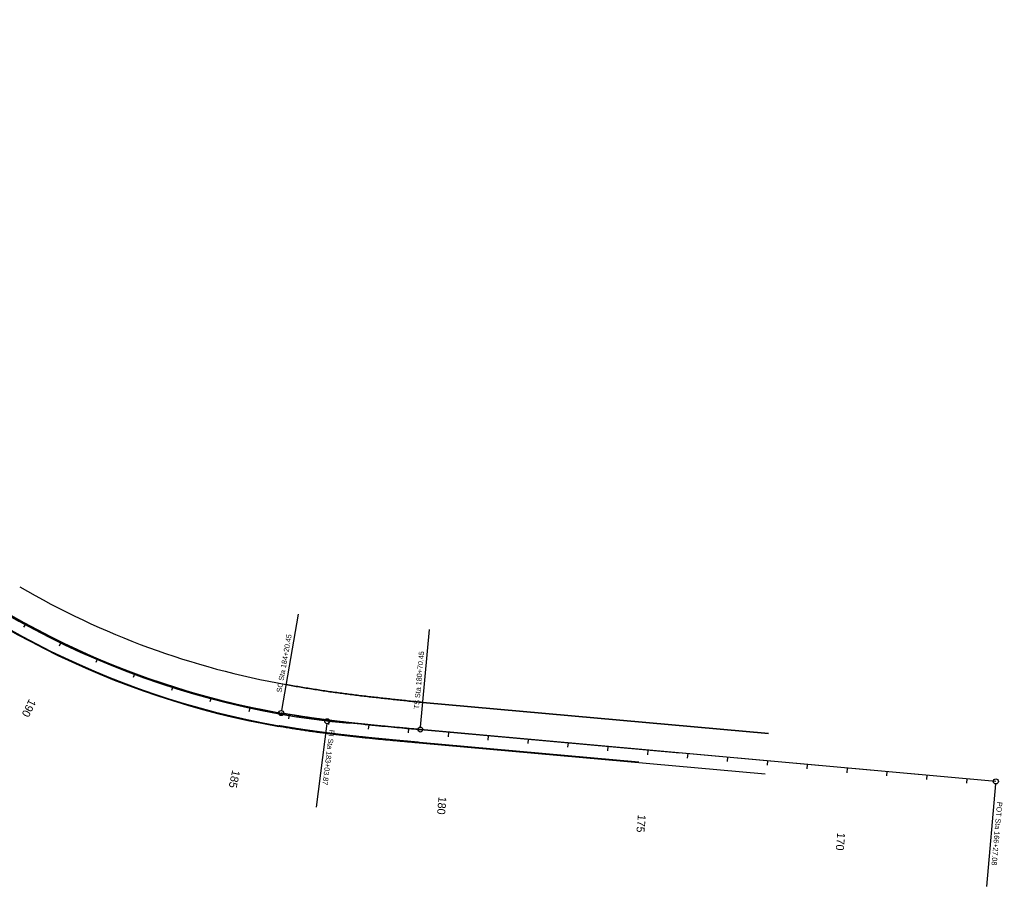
# Model space of a CAD drawing. Extents: x 5180909 to 5237144, y 3695282 to 3720102.
# Drawn here: x 5198956 to 5201411, y 3702372 to 3704537 of the extents above; entities that cross this region are included whole.
import ezdxf

# ---------------------------------------------------------------- set-up
doc = ezdxf.new("R2010")
doc.units = 0
for name, color, linetype in [('Alignment', 7, 'Continuous'), ('brgPreStructureNew', 7, 'Continuous'), ('Default', 7, 'Continuous'), ('DisFieldPoint', 7, 'Continuous'), ('dsnEntrancePaved', 7, 'Continuous'), ('dsnShadingGranular', 7, 'Continuous'), ('dsnSidewalkShadingRamp', 7, 'Continuous'), ('dsnStgShadingPropGrdLim', 7, 'Continuous')]:
    doc.layers.add(name, color=color, linetype=linetype)

msp = doc.modelspace()

# ---------------------------------------------------------------- linework, layer by layer
at = {"layer": 'Alignment'}
msp.add_line((5201394.7, 3702633.9), (5199957.1, 3702763.5), dxfattribs=at)
msp.add_arc((5199969.8, 3704853.2), 2080, 193.5037, 260.0302, dxfattribs=at)
msp.add_open_spline([(5199957.1, 3702763.5), (5199947.4, 3702764.4), (5199928.1, 3702766.1), (5199889.3, 3702769.6), (5199840.9, 3702774.2), (5199782.9, 3702780.3), (5199725, 3702787.1), (5199676.8, 3702793.8), (5199638.4, 3702799.7), (5199619.2, 3702803), (5199609.7, 3702804.7)], degree=3, dxfattribs=at)
at = {"layer": 'brgPreStructureNew'}
msp.add_open_spline([(5199957.5, 3702763.2), (5199956, 3702763.4), (5199954.4, 3702763.5), (5199952.8, 3702763.7), (5199951.3, 3702763.8), (5199949.7, 3702763.9), (5199948.1, 3702764.1), (5199946.5, 3702764.2), (5199945, 3702764.4), (5199943.4, 3702764.5), (5199941.8, 3702764.6), (5199940.3, 3702764.8), (5199938.7, 3702764.9), (5199937.1, 3702765.1), (5199935.6, 3702765.2), (5199934, 3702765.4), (5199932.4, 3702765.5), (5199930.8, 3702765.6), (5199929.3, 3702765.8), (5199927.7, 3702765.9), (5199926.1, 3702766.1), (5199924.6, 3702766.2), (5199923, 3702766.4), (5199921.4, 3702766.5), (5199919.9, 3702766.6), (5199918.3, 3702766.8), (5199916.7, 3702766.9), (5199915.1, 3702767.1), (5199913.6, 3702767.2), (5199912, 3702767.4), (5199910.4, 3702767.5), (5199908.9, 3702767.6), (5199907.3, 3702767.8), (5199905.7, 3702767.9), (5199904.2, 3702768.1), (5199902.6, 3702768.2), (5199901, 3702768.4), (5199899.4, 3702768.5), (5199897.9, 3702768.7), (5199896.3, 3702768.8), (5199894.7, 3702768.9), (5199893.2, 3702769.1), (5199891.6, 3702769.2), (5199890, 3702769.4), (5199888.5, 3702769.5), (5199886.9, 3702769.7), (5199885.3, 3702769.8), (5199883.7, 3702770), (5199882.2, 3702770.1), (5199880.6, 3702770.3), (5199879, 3702770.4), (5199877.5, 3702770.6), (5199875.9, 3702770.7), (5199874.3, 3702770.9), (5199872.8, 3702771), (5199871.2, 3702771.2), (5199869.6, 3702771.3), (5199868, 3702771.5), (5199866.5, 3702771.6), (5199864.9, 3702771.8), (5199863.3, 3702771.9), (5199861.8, 3702772.1), (5199860.2, 3702772.2), (5199858.6, 3702772.4), (5199857.1, 3702772.5), (5199855.5, 3702772.7), (5199853.9, 3702772.8), (5199852.4, 3702773), (5199850.8, 3702773.1), (5199849.2, 3702773.3), (5199847.6, 3702773.4), (5199846.1, 3702773.6), (5199844.5, 3702773.8), (5199842.9, 3702773.9), (5199841.4, 3702774.1), (5199839.8, 3702774.2), (5199838.2, 3702774.4), (5199836.7, 3702774.5), (5199835.1, 3702774.7), (5199833.5, 3702774.9), (5199832, 3702775), (5199830.4, 3702775.2), (5199828.8, 3702775.3), (5199827.3, 3702775.5), (5199825.7, 3702775.7), (5199824.1, 3702775.8), (5199822.5, 3702776), (5199821, 3702776.1), (5199819.4, 3702776.3), (5199817.8, 3702776.5), (5199816.3, 3702776.6), (5199814.7, 3702776.8), (5199813.1, 3702776.9), (5199811.6, 3702777.1), (5199810, 3702777.3), (5199808.4, 3702777.4), (5199806.9, 3702777.6), (5199805.3, 3702777.8), (5199803.7, 3702777.9), (5199802.2, 3702778.1), (5199800.6, 3702778.3), (5199799, 3702778.4), (5199797.5, 3702778.6), (5199795.9, 3702778.8), (5199794.3, 3702779), (5199792.8, 3702779.1), (5199791.2, 3702779.3), (5199789.6, 3702779.5), (5199788.1, 3702779.6), (5199786.5, 3702779.8), (5199784.9, 3702780), (5199783.4, 3702780.2), (5199781.8, 3702780.3), (5199780.2, 3702780.5), (5199778.7, 3702780.7), (5199777.1, 3702780.9), (5199775.5, 3702781), (5199774, 3702781.2), (5199772.4, 3702781.4), (5199770.8, 3702781.6), (5199769.3, 3702781.8), (5199767.7, 3702781.9), (5199766.1, 3702782.1), (5199764.6, 3702782.3), (5199763, 3702782.5), (5199761.4, 3702782.7), (5199759.9, 3702782.9), (5199758.3, 3702783), (5199756.7, 3702783.2), (5199755.2, 3702783.4), (5199753.6, 3702783.6), (5199752, 3702783.8), (5199750.5, 3702784), (5199748.9, 3702784.2), (5199747.3, 3702784.3), (5199745.8, 3702784.5), (5199744.2, 3702784.7), (5199742.6, 3702784.9), (5199741.1, 3702785.1), (5199739.5, 3702785.3), (5199738, 3702785.5), (5199736.4, 3702785.7), (5199734.8, 3702785.9), (5199733.3, 3702786.1), (5199731.7, 3702786.3), (5199730.1, 3702786.5), (5199728.6, 3702786.7), (5199727, 3702786.9), (5199725.4, 3702787.1), (5199723.9, 3702787.3), (5199722.3, 3702787.5), (5199720.7, 3702787.7), (5199719.2, 3702787.9), (5199717.6, 3702788.1), (5199716.1, 3702788.3), (5199714.5, 3702788.5), (5199712.9, 3702788.7), (5199711.4, 3702788.9), (5199709.8, 3702789.1), (5199708.2, 3702789.3), (5199706.7, 3702789.5), (5199705.1, 3702789.7), (5199703.6, 3702790), (5199702, 3702790.2), (5199700.4, 3702790.4), (5199698.9, 3702790.6), (5199697.3, 3702790.8), (5199695.7, 3702791), (5199694.2, 3702791.2), (5199692.6, 3702791.5), (5199691.1, 3702791.7), (5199689.5, 3702791.9), (5199687.9, 3702792.1), (5199686.4, 3702792.3), (5199684.8, 3702792.6), (5199683.3, 3702792.8), (5199681.7, 3702793), (5199680.1, 3702793.2), (5199678.6, 3702793.5), (5199677, 3702793.7), (5199675.5, 3702793.9), (5199673.9, 3702794.1), (5199672.3, 3702794.4), (5199670.8, 3702794.6), (5199669.2, 3702794.8), (5199667.7, 3702795.1), (5199666.1, 3702795.3), (5199664.5, 3702795.5), (5199663, 3702795.8), (5199661.4, 3702796), (5199659.9, 3702796.2), (5199658.3, 3702796.5), (5199656.7, 3702796.7), (5199655.2, 3702797), (5199653.6, 3702797.2), (5199652.1, 3702797.4), (5199650.5, 3702797.7), (5199649, 3702797.9), (5199647.4, 3702798.2), (5199645.8, 3702798.4), (5199644.3, 3702798.7), (5199642.7, 3702798.9), (5199641.2, 3702799.2), (5199639.6, 3702799.4), (5199638.1, 3702799.7), (5199636.5, 3702799.9), (5199634.9, 3702800.2), (5199633.4, 3702800.4), (5199631.8, 3702800.7), (5199630.3, 3702800.9), (5199628.7, 3702801.2), (5199627.2, 3702801.5), (5199625.6, 3702801.7), (5199624.1, 3702802), (5199622.5, 3702802.3), (5199620.9, 3702802.5), (5199619.4, 3702802.8), (5199617.8, 3702803), (5199616.3, 3702803.3), (5199614.7, 3702803.6), (5199613.2, 3702803.9), (5199611.6, 3702804.1), (5199610.1, 3702804.4)], degree=3, dxfattribs=at)
msp.add_open_spline([(5199957.5, 3702763.2), (5199956, 3702763.4), (5199954.4, 3702763.5), (5199952.8, 3702763.7), (5199951.3, 3702763.8), (5199949.7, 3702763.9), (5199948.1, 3702764.1), (5199946.5, 3702764.2), (5199945, 3702764.4), (5199943.4, 3702764.5), (5199941.8, 3702764.6), (5199940.3, 3702764.8), (5199938.7, 3702764.9), (5199937.1, 3702765.1), (5199935.6, 3702765.2), (5199934, 3702765.4), (5199932.4, 3702765.5), (5199930.8, 3702765.6), (5199929.3, 3702765.8), (5199927.7, 3702765.9), (5199926.1, 3702766.1), (5199924.6, 3702766.2), (5199923, 3702766.4), (5199921.4, 3702766.5), (5199919.9, 3702766.6), (5199918.3, 3702766.8), (5199916.7, 3702766.9), (5199915.1, 3702767.1), (5199913.6, 3702767.2), (5199912, 3702767.4), (5199910.4, 3702767.5), (5199908.9, 3702767.6), (5199907.3, 3702767.8), (5199905.7, 3702767.9), (5199904.2, 3702768.1), (5199902.6, 3702768.2), (5199901, 3702768.4), (5199899.4, 3702768.5), (5199897.9, 3702768.7), (5199896.3, 3702768.8), (5199894.7, 3702768.9), (5199893.2, 3702769.1), (5199891.6, 3702769.2), (5199890, 3702769.4), (5199888.5, 3702769.5), (5199886.9, 3702769.7), (5199885.3, 3702769.8), (5199883.7, 3702770), (5199882.2, 3702770.1), (5199880.6, 3702770.3), (5199879, 3702770.4), (5199877.5, 3702770.6), (5199875.9, 3702770.7), (5199874.3, 3702770.9), (5199872.8, 3702771), (5199871.2, 3702771.2), (5199869.6, 3702771.3), (5199868, 3702771.5), (5199866.5, 3702771.6), (5199864.9, 3702771.8), (5199863.3, 3702771.9), (5199861.8, 3702772.1), (5199860.2, 3702772.2), (5199858.6, 3702772.4), (5199857.1, 3702772.5), (5199855.5, 3702772.7), (5199853.9, 3702772.8), (5199852.4, 3702773), (5199850.8, 3702773.1), (5199849.2, 3702773.3), (5199847.6, 3702773.4), (5199846.1, 3702773.6), (5199844.5, 3702773.8), (5199842.9, 3702773.9), (5199841.4, 3702774.1), (5199839.8, 3702774.2), (5199838.2, 3702774.4), (5199836.7, 3702774.5), (5199835.1, 3702774.7), (5199833.5, 3702774.9), (5199832, 3702775), (5199830.4, 3702775.2), (5199828.8, 3702775.3), (5199827.3, 3702775.5), (5199825.7, 3702775.7), (5199824.1, 3702775.8), (5199822.5, 3702776), (5199821, 3702776.1), (5199819.4, 3702776.3), (5199817.8, 3702776.5), (5199816.3, 3702776.6), (5199814.7, 3702776.8), (5199813.1, 3702776.9), (5199811.6, 3702777.1), (5199810, 3702777.3), (5199808.4, 3702777.4), (5199806.9, 3702777.6), (5199805.3, 3702777.8), (5199803.7, 3702777.9), (5199802.2, 3702778.1), (5199800.6, 3702778.3), (5199799, 3702778.4), (5199797.5, 3702778.6), (5199795.9, 3702778.8), (5199794.3, 3702779), (5199792.8, 3702779.1), (5199791.2, 3702779.3), (5199789.6, 3702779.5), (5199788.1, 3702779.6), (5199786.5, 3702779.8), (5199784.9, 3702780), (5199783.4, 3702780.2), (5199781.8, 3702780.3), (5199780.2, 3702780.5), (5199778.7, 3702780.7), (5199777.1, 3702780.9), (5199775.5, 3702781), (5199774, 3702781.2), (5199772.4, 3702781.4), (5199770.8, 3702781.6), (5199769.3, 3702781.8), (5199767.7, 3702781.9), (5199766.1, 3702782.1), (5199764.6, 3702782.3), (5199763, 3702782.5), (5199761.4, 3702782.7), (5199759.9, 3702782.9), (5199758.3, 3702783), (5199756.7, 3702783.2), (5199755.2, 3702783.4), (5199753.6, 3702783.6), (5199752, 3702783.8), (5199750.5, 3702784), (5199748.9, 3702784.2), (5199747.3, 3702784.3), (5199745.8, 3702784.5), (5199744.2, 3702784.7), (5199742.6, 3702784.9), (5199741.1, 3702785.1), (5199739.5, 3702785.3), (5199738, 3702785.5), (5199736.4, 3702785.7), (5199734.8, 3702785.9), (5199733.3, 3702786.1), (5199731.7, 3702786.3), (5199730.1, 3702786.5), (5199728.6, 3702786.7), (5199727, 3702786.9), (5199725.4, 3702787.1), (5199723.9, 3702787.3), (5199722.3, 3702787.5), (5199720.7, 3702787.7), (5199719.2, 3702787.9), (5199717.6, 3702788.1), (5199716.1, 3702788.3), (5199714.5, 3702788.5), (5199712.9, 3702788.7), (5199711.4, 3702788.9), (5199709.8, 3702789.1), (5199708.2, 3702789.3), (5199706.7, 3702789.5), (5199705.1, 3702789.7), (5199703.6, 3702790), (5199702, 3702790.2), (5199700.4, 3702790.4), (5199698.9, 3702790.6), (5199697.3, 3702790.8), (5199695.7, 3702791), (5199694.2, 3702791.2), (5199692.6, 3702791.5), (5199691.1, 3702791.7), (5199689.5, 3702791.9), (5199687.9, 3702792.1), (5199686.4, 3702792.3), (5199684.8, 3702792.6), (5199683.3, 3702792.8), (5199681.7, 3702793), (5199680.1, 3702793.2), (5199678.6, 3702793.5), (5199677, 3702793.7), (5199675.5, 3702793.9), (5199673.9, 3702794.1), (5199672.3, 3702794.4), (5199670.8, 3702794.6), (5199669.2, 3702794.8), (5199667.7, 3702795.1), (5199666.1, 3702795.3), (5199664.5, 3702795.5), (5199663, 3702795.8), (5199661.4, 3702796), (5199659.9, 3702796.2), (5199658.3, 3702796.5), (5199656.7, 3702796.7), (5199655.2, 3702797), (5199653.6, 3702797.2), (5199652.1, 3702797.4), (5199650.5, 3702797.7), (5199649, 3702797.9), (5199647.4, 3702798.2), (5199645.8, 3702798.4), (5199644.3, 3702798.7), (5199642.7, 3702798.9), (5199641.2, 3702799.2), (5199639.6, 3702799.4), (5199638.1, 3702799.7), (5199636.5, 3702799.9), (5199634.9, 3702800.2), (5199633.4, 3702800.4), (5199631.8, 3702800.7), (5199630.3, 3702800.9), (5199628.7, 3702801.2), (5199627.2, 3702801.5), (5199625.6, 3702801.7), (5199624.1, 3702802), (5199622.5, 3702802.3), (5199620.9, 3702802.5), (5199619.4, 3702802.8), (5199617.8, 3702803), (5199616.3, 3702803.3), (5199614.7, 3702803.6), (5199613.2, 3702803.9), (5199611.6, 3702804.1), (5199610.1, 3702804.4)], degree=3, dxfattribs=at)
at = {"layer": 'Default'}
msp.add_arc((5199969.8, 3704853.2), 2080, 193.5037, 260.0302, dxfattribs=at)
at = {"layer": 'DisFieldPoint'}
for p, q in [((5199604.6, 3702772.9), (5199604.5, 3702772.9)), ((5199604.6, 3702772.9), (5199604.6, 3702772.9)), ((5200605, 3702704.8), (5199957.5, 3702763.2)), ((5200502.5, 3702681.9), (5199954.7, 3702731.4))]:
    msp.add_line(p, q, dxfattribs=at)
for radius in [2083.5, 2115.5]:
    msp.add_arc((5199970.6, 3704856.4), radius, 191.1921, 260.0343, dxfattribs=at)
msp.add_open_spline([(5199954.7, 3702731.4), (5199953.1, 3702731.5), (5199951.5, 3702731.6), (5199949.9, 3702731.8), (5199948.4, 3702731.9), (5199946.8, 3702732.1), (5199945.2, 3702732.2), (5199943.7, 3702732.3), (5199942.1, 3702732.5), (5199940.5, 3702732.6), (5199939, 3702732.8), (5199937.4, 3702732.9), (5199935.8, 3702733.1), (5199934.2, 3702733.2), (5199932.7, 3702733.3), (5199931.1, 3702733.5), (5199929.5, 3702733.6), (5199928, 3702733.8), (5199926.4, 3702733.9), (5199924.8, 3702734.1), (5199923.2, 3702734.2), (5199921.7, 3702734.3), (5199920.1, 3702734.5), (5199918.5, 3702734.6), (5199916.9, 3702734.8), (5199915.4, 3702734.9), (5199913.8, 3702735.1), (5199912.2, 3702735.2), (5199910.7, 3702735.3), (5199909.1, 3702735.5), (5199907.5, 3702735.6), (5199905.9, 3702735.8), (5199904.4, 3702735.9), (5199902.8, 3702736.1), (5199901.2, 3702736.2), (5199899.6, 3702736.4), (5199898.1, 3702736.5), (5199896.5, 3702736.6), (5199894.9, 3702736.8), (5199893.3, 3702736.9), (5199891.8, 3702737.1), (5199890.2, 3702737.2), (5199888.6, 3702737.4), (5199887, 3702737.5), (5199885.5, 3702737.7), (5199883.9, 3702737.8), (5199882.3, 3702738), (5199880.7, 3702738.1), (5199879.2, 3702738.3), (5199877.6, 3702738.4), (5199876, 3702738.6), (5199874.4, 3702738.7), (5199872.9, 3702738.9), (5199871.3, 3702739), (5199869.7, 3702739.2), (5199868.1, 3702739.3), (5199866.6, 3702739.5), (5199865, 3702739.6), (5199863.4, 3702739.8), (5199861.8, 3702739.9), (5199860.3, 3702740.1), (5199858.7, 3702740.2), (5199857.1, 3702740.4), (5199855.5, 3702740.5), (5199854, 3702740.7), (5199852.4, 3702740.8), (5199850.8, 3702741), (5199849.2, 3702741.1), (5199847.7, 3702741.3), (5199846.1, 3702741.4), (5199844.5, 3702741.6), (5199842.9, 3702741.8), (5199841.4, 3702741.9), (5199839.8, 3702742.1), (5199838.2, 3702742.2), (5199836.6, 3702742.4), (5199835, 3702742.5), (5199833.5, 3702742.7), (5199831.9, 3702742.9), (5199830.3, 3702743), (5199828.7, 3702743.2), (5199827.2, 3702743.3), (5199825.6, 3702743.5), (5199824, 3702743.7), (5199822.4, 3702743.8), (5199820.9, 3702744), (5199819.3, 3702744.1), (5199817.7, 3702744.3), (5199816.1, 3702744.5), (5199814.5, 3702744.6), (5199813, 3702744.8), (5199811.4, 3702745), (5199809.8, 3702745.1), (5199808.2, 3702745.3), (5199806.7, 3702745.5), (5199805.1, 3702745.6), (5199803.5, 3702745.8), (5199801.9, 3702746), (5199800.3, 3702746.1), (5199798.8, 3702746.3), (5199797.2, 3702746.5), (5199795.6, 3702746.6), (5199794, 3702746.8), (5199792.4, 3702747), (5199790.9, 3702747.1), (5199789.3, 3702747.3), (5199787.7, 3702747.5), (5199786.1, 3702747.7), (5199784.6, 3702747.8), (5199783, 3702748), (5199781.4, 3702748.2), (5199779.8, 3702748.4), (5199778.2, 3702748.5), (5199776.7, 3702748.7), (5199775.1, 3702748.9), (5199773.5, 3702749.1), (5199771.9, 3702749.2), (5199770.3, 3702749.4), (5199768.8, 3702749.6), (5199767.2, 3702749.8), (5199765.6, 3702750), (5199764, 3702750.2), (5199762.4, 3702750.3), (5199760.9, 3702750.5), (5199759.3, 3702750.7), (5199757.7, 3702750.9), (5199756.1, 3702751.1), (5199754.5, 3702751.3), (5199753, 3702751.4), (5199751.4, 3702751.6), (5199749.8, 3702751.8), (5199748.2, 3702752), (5199746.7, 3702752.2), (5199745.1, 3702752.4), (5199743.5, 3702752.6), (5199741.9, 3702752.8), (5199740.3, 3702753), (5199738.8, 3702753.2), (5199737.2, 3702753.4), (5199735.6, 3702753.5), (5199734, 3702753.7), (5199732.4, 3702753.9), (5199730.9, 3702754.1), (5199729.3, 3702754.3), (5199727.7, 3702754.5), (5199726.1, 3702754.7), (5199724.5, 3702754.9), (5199723, 3702755.1), (5199721.4, 3702755.3), (5199719.8, 3702755.5), (5199718.2, 3702755.7), (5199716.6, 3702755.9), (5199715.1, 3702756.1), (5199713.5, 3702756.4), (5199711.9, 3702756.6), (5199710.3, 3702756.8), (5199708.7, 3702757), (5199707.2, 3702757.2), (5199705.6, 3702757.4), (5199704, 3702757.6), (5199702.4, 3702757.8), (5199700.8, 3702758), (5199699.3, 3702758.2), (5199697.7, 3702758.5), (5199696.1, 3702758.7), (5199694.5, 3702758.9), (5199692.9, 3702759.1), (5199691.4, 3702759.3), (5199689.8, 3702759.5), (5199688.2, 3702759.8), (5199686.6, 3702760), (5199685, 3702760.2), (5199683.5, 3702760.4), (5199681.9, 3702760.7), (5199680.3, 3702760.9), (5199678.7, 3702761.1), (5199677.1, 3702761.3), (5199675.6, 3702761.6), (5199674, 3702761.8), (5199672.4, 3702762), (5199670.8, 3702762.2), (5199669.2, 3702762.5), (5199667.7, 3702762.7), (5199666.1, 3702762.9), (5199664.5, 3702763.2), (5199662.9, 3702763.4), (5199661.3, 3702763.7), (5199659.8, 3702763.9), (5199658.2, 3702764.1), (5199656.6, 3702764.4), (5199655, 3702764.6), (5199653.5, 3702764.8), (5199651.9, 3702765.1), (5199650.3, 3702765.3), (5199648.7, 3702765.6), (5199647.1, 3702765.8), (5199645.6, 3702766.1), (5199644, 3702766.3), (5199642.4, 3702766.6), (5199640.8, 3702766.8), (5199639.2, 3702767.1), (5199637.7, 3702767.3), (5199636.1, 3702767.6), (5199634.5, 3702767.8), (5199632.9, 3702768.1), (5199631.4, 3702768.3), (5199629.8, 3702768.6), (5199628.2, 3702768.9), (5199626.6, 3702769.1), (5199625, 3702769.4), (5199623.5, 3702769.6), (5199621.9, 3702769.9), (5199620.3, 3702770.2), (5199618.7, 3702770.4), (5199617.2, 3702770.7), (5199615.6, 3702771), (5199614, 3702771.2), (5199612.4, 3702771.5), (5199610.9, 3702771.8), (5199609.2, 3702772.1), (5199607.7, 3702772.3), (5199606.1, 3702772.6), (5199604.6, 3702772.9)], degree=3, dxfattribs=at)
at = {"layer": 'dsnEntrancePaved'}
msp.add_arc((5199969.8, 3704853.2), 2080, 193.5037, 260.0302, dxfattribs=at)
msp.add_open_spline([(5199609.7, 3702804.7), (5199624, 3702802.1), (5199652.8, 3702797.4), (5199710.5, 3702788.9), (5199782.9, 3702780.1), (5199855.5, 3702772.8), (5199913.5, 3702767.4), (5199942.6, 3702764.8), (5199957.1, 3702763.5)], degree=3, dxfattribs=at)
at = {"layer": 'dsnShadingGranular'}
for p, q in [((5200826.4, 3702753.4), (5199963.2, 3702831.2)), ((5199963.2, 3702831.2), (5200826.4, 3702753.4)), ((5201394.7, 3702633.9), (5199780.9, 3702779.4)), ((5201394.7, 3702633.9), (5199957.1, 3702763.5)), ((5200818.3, 3702651.7), (5199954.1, 3702729.6))]:
    msp.add_line(p, q, dxfattribs=at)
for centre, radius, start, end in [((5199967.6, 3704851), 2080, 188.6831, 264.8508), ((5199969.8, 3704853.2), 2114, 193.5037, 260.0302), ((5199969.8, 3704853.2), 2007.5, 239.675, 260.0302), ((5199969.8, 3704853.2), 2007.5, 239.675, 260.0302)]:
    msp.add_arc(centre, radius, start, end, dxfattribs=at)
for points in [[(5199622.2, 3702876.1), (5199627.7, 3702875), (5199638.8, 3702872.9), (5199655.5, 3702870), (5199672.2, 3702867.2), (5199689, 3702864.5), (5199705.9, 3702861.9), (5199722.8, 3702859.3), (5199739.7, 3702856.9), (5199756.7, 3702854.6), (5199773.7, 3702852.4), (5199790.7, 3702850.2), (5199807.8, 3702848.1), (5199824.9, 3702846.1), (5199842.1, 3702844.1), (5199859.3, 3702842.2), (5199876.6, 3702840.3), (5199893.8, 3702838.4), (5199911.1, 3702836.6), (5199928.5, 3702834.8), (5199945.8, 3702833), (5199957.4, 3702831.8), (5199963.2, 3702831.2)], [(5199954.1, 3702729.6), (5199949.2, 3702730.1), (5199939.5, 3702730.9), (5199925, 3702732.3), (5199910.4, 3702733.6), (5199895.9, 3702734.9), (5199881.3, 3702736.3), (5199866.7, 3702737.6), (5199852.2, 3702739), (5199837.6, 3702740.5), (5199823, 3702742), (5199808.4, 3702743.5), (5199793.8, 3702745), (5199779.2, 3702746.6), (5199764.6, 3702748.3), (5199749.9, 3702750), (5199735.3, 3702751.8), (5199720.7, 3702753.6), (5199706.1, 3702755.5), (5199691.4, 3702757.5), (5199676.8, 3702759.5), (5199662.2, 3702761.7), (5199647.6, 3702763.9), (5199633, 3702766.2), (5199618.4, 3702768.6), (5199608.6, 3702770.3), (5199603.8, 3702771.2)]]:
    msp.add_open_spline(points, degree=3, dxfattribs=at)
at = {"layer": 'dsnSidewalkShadingRamp'}
for p, q in [((5198971.3, 3703028.6), (5198966, 3703018.9)), ((5199610.7, 3702810.8), (5199653.1, 3703051.9)), ((5199957.7, 3702769.7), (5199979.7, 3703013.7)), ((5199060.1, 3702982.7), (5199054.7, 3702971.7)), ((5199151, 3702941.1), (5199146.7, 3702931)), ((5199243.9, 3702904), (5199240, 3702893.7)), ((5199338.4, 3702871.4), (5199335.1, 3702860.9)), ((5199434.4, 3702843.3), (5199431.5, 3702832.7)), ((5199531.6, 3702819.9), (5199529, 3702807.9)), ((5199629.8, 3702801.2), (5199628, 3702790.4)), ((5199728.8, 3702786.8), (5199727.4, 3702775.9)), ((5199723.8, 3702778.2), (5199697.1, 3702569.2)), ((5199828.1, 3702775.6), (5199827, 3702764.7)), ((5199927.7, 3702766.1), (5199926.7, 3702755.2)), ((5200027.3, 3702757.2), (5200026.2, 3702745)), ((5200126.9, 3702748.2), (5200125.9, 3702737.2)), ((5200226.5, 3702739.2), (5200225.5, 3702728.3)), ((5200326.1, 3702730.2), (5200325.1, 3702719.3)), ((5200425.7, 3702721.3), (5200424.7, 3702710.3)), ((5200525.3, 3702712.3), (5200524.2, 3702700.1)), ((5200624.9, 3702703.3), (5200623.9, 3702692.4)), ((5200724.4, 3702694.3), (5200723.5, 3702683.4)), ((5200824, 3702685.4), (5200823.1, 3702674.4)), ((5200923.6, 3702676.4), (5200922.7, 3702665.4)), ((5201023.2, 3702667.4), (5201022.1, 3702655.2)), ((5201122.8, 3702658.4), (5201121.8, 3702647.5)), ((5201222.4, 3702649.5), (5201221.4, 3702638.5)), ((5201322, 3702640.5), (5201321, 3702629.5)), ((5201394.1, 3702627.7), (5201371, 3702371.8))]:
    msp.add_line(p, q, dxfattribs=at)
for centre in [(5199609.7, 3702804.7), (5199724.6, 3702784.4), (5199957.1, 3702763.5), (5201394.7, 3702633.9)]:
    msp.add_circle(centre, 6.25, dxfattribs=at)
at = {"layer": 'dsnStgShadingPropGrdLim'}
for points in [[(5199963.2, 3702831.2), (5199957.4, 3702831.8), (5199945.8, 3702833), (5199928.5, 3702834.8), (5199911.1, 3702836.6), (5199893.8, 3702838.4), (5199876.6, 3702840.3), (5199859.3, 3702842.2), (5199842.1, 3702844.1), (5199824.9, 3702846.1), (5199807.8, 3702848.1), (5199790.7, 3702850.2), (5199773.7, 3702852.4), (5199756.7, 3702854.6), (5199739.7, 3702856.9), (5199722.8, 3702859.3), (5199705.9, 3702861.9), (5199689, 3702864.5), (5199672.2, 3702867.2), (5199655.5, 3702870), (5199638.8, 3702872.9), (5199627.7, 3702875), (5199622.2, 3702876.1)], [(5199957.1, 3702763.5), (5199942.6, 3702764.8), (5199913.5, 3702767.4), (5199855.5, 3702772.8), (5199782.9, 3702780.1), (5199710.5, 3702788.9), (5199652.8, 3702797.4), (5199624, 3702802.1), (5199609.7, 3702804.7)]]:
    msp.add_open_spline(points, degree=3, dxfattribs=at)

# ---------------------------------------------------------------- texts
at = {"layer": 'dsnSidewalkShadingRamp'}
for s, height, rotation, p in [('SC Sta 184+20.45', 13, 80.0302, (5199610.4, 3702855.3)), ('TS Sta 180+70.45', 13, 84.8508, (5199953.6, 3702814)), ('190', 20, 244.0658, (5198980.1, 3702841.2)), ('PI Sta 183+03.87', 13, 262.7067, (5199730, 3702763.6)), ('185', 20, 257.8389, (5199487.6, 3702663.4)), ('180', 20, 264.8508, (5200002.8, 3702596.5)), ('POT Sta 166+27.08', 13, 264.8508, (5201398.1, 3702583.4)), ('175', 20, 264.8508, (5200500.7, 3702551.6)), ('170', 20, 264.8508, (5200998.7, 3702506.7))]:
    msp.add_text(s, height=height, rotation=rotation, dxfattribs=at).set_placement(p)

doc.saveas('drawing.dxf')
